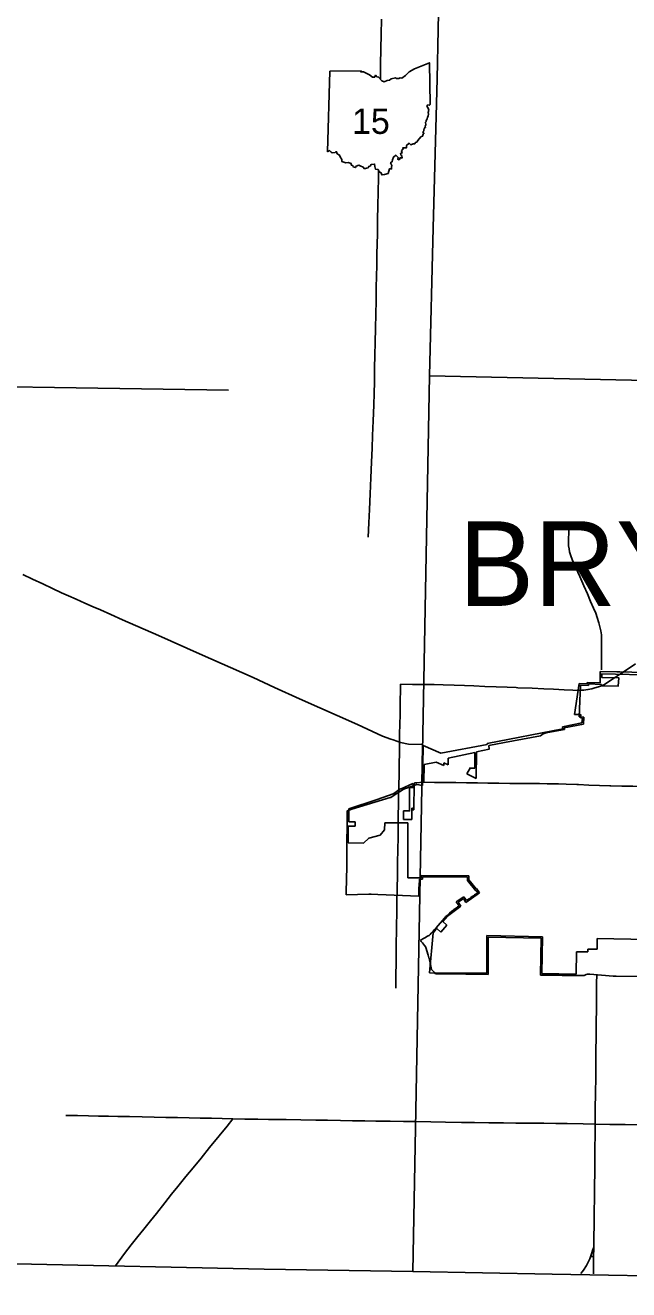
# Model space of a CAD drawing. Extents: x -232 to 448, y 619 to 1059.
# Drawn here: x -131.55 to -109.62, y 850.56 to 896.53 of the extents above; entities that cross this region are included whole.
import ezdxf

# ---------------------------------------------------------------- set-up
doc = ezdxf.new("R2010")
doc.units = 0
doc.layers.add('Default', color=7, linetype='Continuous')

msp = doc.modelspace()

# ---------------------------------------------------------------- linework, layer by layer
at = {"layer": 'Default'}
for p, q in [((-120.564, 891.931), (-120.482, 894.86)), ((-120.564, 891.931), (-120.482, 894.86)), ((-111.422, 872.599), (-111.588, 871.475)), ((-111.129, 872.588), (-111.422, 872.599)), ((-111.378, 872.546), (-111.419, 871.39)), ((-111.079, 872.535), (-111.378, 872.546)), ((-111.127, 872.641), (-111.129, 872.588)), ((-110.655, 872.624), (-111.127, 872.641)), ((-111.078, 872.588), (-111.079, 872.535)), ((-110.606, 872.571), (-111.078, 872.588)), ((-110.608, 872.519), (-110.606, 872.571)), ((-111.321, 871.168), (-112.028, 871.028)), ((-111.263, 871.128), (-111.968, 870.987)), ((-111.588, 871.475), (-111.364, 871.471)), ((-111.419, 871.39), (-111.253, 871.384)), ((-111.364, 871.471), (-111.378, 871.359)), ((-111.378, 871.359), (-111.302, 871.339)), ((-111.302, 871.339), (-111.321, 871.168)), ((-111.253, 871.384), (-111.263, 871.128)), ((-112.013, 870.952), (-114.762, 870.422)), ((-112.028, 871.028), (-112.013, 870.952)), ((-111.968, 870.987), (-111.956, 870.928)), ((-116.618, 869.744), (-117.06, 869.655)), ((-116.336, 869.616), (-116.618, 869.744)), ((-116.189, 869.894), (-116.189, 869.65)), ((-117.06, 869.655), (-117.065, 869.013)), ((-116.189, 869.65), (-116.336, 869.722)), ((-115.508, 869.317), (-115.374, 869.546)), ((-115.166, 869.147), (-115.508, 869.317)), ((-117.417, 868.979), (-117.428, 868.011)), ((-118.769, 868.391), (-119.787, 868.043)), ((-119.787, 868.043), (-119.79, 867.569)), ((-117.806, 867.657), (-117.807, 867.969)), ((-117.498, 868.073), (-117.498, 867.657)), ((-119.79, 867.569), (-119.559, 867.569)), ((-119.559, 867.569), (-119.559, 867.411)), ((-118.493, 867.279), (-118.49, 867.536)), ((-118.49, 867.536), (-117.644, 867.533)), ((-117.498, 867.657), (-117.806, 867.657)), ((-117.644, 867.533), (-117.652, 865.542)), ((-119.812, 867.416), (-119.817, 866.805)), ((-119.559, 867.411), (-119.812, 867.416)), ((-119.256, 866.795), (-119.062, 866.982)), ((-119.062, 866.982), (-118.657, 867.083)), ((-118.657, 867.083), (-118.493, 867.279)), ((-119.817, 866.805), (-119.256, 866.795)), ((-117.167, 865.54), (-117.166, 865.622)), ((-117.166, 865.622), (-115.427, 865.616)), ((-115.427, 865.616), (-115.429, 865.46)), ((-117.652, 865.542), (-117.167, 865.54)), ((-117.225, 865.489), (-117.116, 865.489)), ((-117.116, 865.489), (-117.115, 865.571)), ((-117.115, 865.571), (-115.479, 865.564)), ((-115.479, 865.564), (-115.481, 865.442)), ((-115.481, 865.442), (-115.177, 865.071)), ((-115.429, 865.46), (-115.167, 865.14)), ((-115.167, 865.14), (-115.154, 865.149)), ((-115.154, 865.149), (-115.046, 864.996)), ((-115.618, 864.853), (-115.888, 864.665)), ((-115.631, 864.781), (-115.817, 864.652)), ((-115.538, 864.646), (-115.631, 864.781)), ((-115.518, 864.708), (-115.618, 864.853)), ((-115.177, 865.071), (-115.167, 865.078)), ((-115.167, 865.078), (-115.108, 864.995)), ((-115.888, 864.665), (-115.787, 864.519)), ((-115.817, 864.652), (-115.719, 864.511)), ((-116.23, 863.82), (-116.448, 863.56)), ((-116.376, 863.945), (-116.23, 863.82)), ((-116.731, 863.544), (-116.859, 862.083)), ((-116.448, 863.56), (-116.594, 863.696)), ((-114.775, 862.075), (-114.775, 863.438)), ((-114.775, 863.438), (-112.75, 863.395)), ((-114.724, 862.023), (-114.724, 863.386)), ((-114.724, 863.386), (-112.802, 863.345)), ((-112.802, 863.345), (-112.831, 862.001)), ((-112.75, 863.395), (-112.778, 862.054)), ((-110.772, 862.941), (-110.77, 863.327)), ((-110.77, 863.327), (-108.941, 863.29)), ((-111.532, 862.04), (-111.522, 862.847)), ((-111.522, 862.847), (-111.112, 862.842)), ((-111.112, 862.842), (-111.111, 862.945)), ((-111.111, 862.945), (-110.772, 862.941)), ((-116.859, 862.083), (-114.775, 862.075)), ((-112.778, 862.054), (-111.532, 862.04))]:
    msp.add_line(p, q, dxfattribs=at)
for points in [[(-115.954, 922.545), (-116.114, 916.14), (-116.231, 910.823), (-116.342, 905.4), (-116.47, 899.975), (-116.579, 894.589), (-116.727, 889.174), (-116.86, 883.788)], [(-118.603, 896.759), (-118.617, 896.197), (-118.625, 895.675), (-118.637, 895.113), (-118.648, 894.57)], [(-120.482, 894.86), (-119.346, 894.879), (-119.364, 894.844), (-119.256, 894.836), (-119.143, 894.774), (-119.046, 894.734), (-118.928, 894.641), (-118.858, 894.642), (-118.828, 894.718), (-118.774, 894.659), (-118.71, 894.649), (-118.599, 894.509), (-118.508, 894.478), (-118.398, 894.526), (-118.316, 894.534), (-118.257, 894.582), (-118.101, 894.622), (-118.057, 894.598), (-117.975, 894.603), (-117.933, 894.621), (-117.861, 894.605), (-117.734, 894.711), (-117.604, 894.837), (-117.403, 894.955), (-117.103, 895.068), (-116.866, 895.168), (-116.832, 893.648)], [(-120.482, 894.86), (-119.346, 894.879), (-119.364, 894.844), (-119.256, 894.836), (-119.143, 894.774), (-119.046, 894.734), (-118.928, 894.641), (-118.858, 894.642), (-118.828, 894.718), (-118.774, 894.659), (-118.71, 894.649), (-118.599, 894.509), (-118.508, 894.478), (-118.398, 894.526), (-118.316, 894.534), (-118.257, 894.582), (-118.101, 894.622), (-118.057, 894.598), (-117.975, 894.603), (-117.933, 894.621), (-117.861, 894.605), (-117.734, 894.711), (-117.604, 894.837), (-117.403, 894.955), (-117.103, 895.068), (-116.866, 895.168), (-116.832, 893.648)], [(-116.832, 893.648), (-116.867, 893.627), (-116.921, 893.637), (-116.958, 893.594), (-116.913, 893.523), (-116.891, 893.448), (-116.91, 893.365), (-116.892, 893.297), (-116.904, 893.24), (-116.939, 893.183), (-116.95, 893.128), (-116.979, 893.071), (-116.977, 893.039), (-117.005, 893.014), (-117, 892.919), (-117.014, 892.866), (-117.009, 892.821), (-117.054, 892.809), (-117.044, 892.771), (-117.072, 892.742), (-117.066, 892.692), (-117.099, 892.661), (-117.067, 892.597), (-117.092, 892.577), (-117.113, 892.499), (-117.171, 892.483), (-117.287, 892.341), (-117.327, 892.288), (-117.373, 892.275), (-117.399, 892.219), (-117.455, 892.219), (-117.54, 892.181), (-117.595, 892.247), (-117.692, 892.168), (-117.703, 892.076), (-117.826, 892.079), (-117.821, 892.033), (-117.848, 892.02), (-117.873, 891.973), (-117.858, 891.891), (-117.916, 891.87), (-117.909, 891.822), (-117.872, 891.793), (-117.856, 891.702), (-117.917, 891.721), (-117.966, 891.644), (-118.018, 891.662), (-118.001, 891.727), (-118.087, 891.805), (-118.169, 891.742), (-118.212, 891.642), (-118.213, 891.575), (-118.274, 891.534), (-118.235, 891.439), (-118.242, 891.373), (-118.24, 891.311), (-118.317, 891.313), (-118.363, 891.145)], [(-116.832, 893.648), (-116.867, 893.627), (-116.921, 893.637), (-116.958, 893.594), (-116.913, 893.523), (-116.891, 893.448), (-116.91, 893.365), (-116.892, 893.297), (-116.904, 893.24), (-116.939, 893.183), (-116.95, 893.128), (-116.979, 893.071), (-116.977, 893.039), (-117.005, 893.014), (-117, 892.919), (-117.014, 892.866), (-117.009, 892.821), (-117.054, 892.809), (-117.044, 892.771), (-117.072, 892.742), (-117.066, 892.692), (-117.099, 892.661), (-117.067, 892.597), (-117.092, 892.577), (-117.113, 892.499), (-117.171, 892.483), (-117.287, 892.341), (-117.327, 892.288), (-117.373, 892.275), (-117.399, 892.219), (-117.455, 892.219), (-117.54, 892.181), (-117.595, 892.247), (-117.692, 892.168), (-117.703, 892.076), (-117.826, 892.079), (-117.821, 892.033), (-117.848, 892.02), (-117.873, 891.973), (-117.858, 891.891), (-117.916, 891.87), (-117.909, 891.822), (-117.872, 891.793), (-117.856, 891.702), (-117.917, 891.721), (-117.966, 891.644), (-118.018, 891.662), (-118.001, 891.727), (-118.087, 891.805), (-118.169, 891.742), (-118.212, 891.642), (-118.213, 891.575), (-118.274, 891.534), (-118.235, 891.439), (-118.242, 891.373), (-118.24, 891.311), (-118.317, 891.313), (-118.363, 891.145)], [(-118.363, 891.145), (-118.496, 891.113), (-118.588, 891.094), (-118.62, 891.17), (-118.686, 891.21), (-118.729, 891.287), (-118.823, 891.298), (-118.846, 891.403), (-118.856, 891.489), (-118.985, 891.468), (-119.021, 891.415), (-119.067, 891.401), (-119.093, 891.349), (-119.156, 891.344), (-119.223, 891.319), (-119.267, 891.371), (-119.377, 891.423), (-119.426, 891.45), (-119.529, 891.408), (-119.551, 891.359), (-119.634, 891.381), (-119.653, 891.436), (-119.703, 891.452), (-119.714, 891.51), (-119.82, 891.541), (-119.901, 891.529), (-120.045, 891.576), (-120.053, 891.653), (-120.102, 891.746), (-120.128, 891.811), (-120.219, 891.861), (-120.237, 891.938), (-120.266, 891.936), (-120.292, 891.904), (-120.393, 891.89), (-120.433, 891.922), (-120.49, 891.976), (-120.564, 891.931)], [(-118.363, 891.145), (-118.496, 891.113), (-118.588, 891.094), (-118.62, 891.17), (-118.686, 891.21), (-118.729, 891.287), (-118.823, 891.298), (-118.846, 891.403), (-118.856, 891.489), (-118.985, 891.468), (-119.021, 891.415), (-119.067, 891.401), (-119.093, 891.349), (-119.156, 891.344), (-119.223, 891.319), (-119.267, 891.371), (-119.377, 891.423), (-119.426, 891.45), (-119.529, 891.408), (-119.551, 891.359), (-119.634, 891.381), (-119.653, 891.436), (-119.703, 891.452), (-119.714, 891.51), (-119.82, 891.541), (-119.901, 891.529), (-120.045, 891.576), (-120.053, 891.653), (-120.102, 891.746), (-120.128, 891.811), (-120.219, 891.861), (-120.237, 891.938), (-120.266, 891.936), (-120.292, 891.904), (-120.393, 891.89), (-120.433, 891.922), (-120.49, 891.976), (-120.564, 891.931)], [(-118.714, 891.261), (-118.719, 890.97), (-118.725, 890.484), (-118.737, 889.96), (-118.747, 889.489), (-118.754, 888.952), (-118.761, 888.578), (-118.773, 888.226), (-118.779, 887.817), (-118.785, 887.4), (-118.797, 887.007), (-118.805, 886.511), (-118.813, 886.028), (-118.825, 885.526), (-118.836, 885), (-118.845, 884.541), (-118.855, 884.066), (-118.863, 883.556), (-118.875, 883.163), (-118.888, 882.721), (-118.912, 882.15), (-118.929, 881.621), (-118.951, 881.159), (-118.97, 880.651), (-118.993, 880.086), (-119.022, 879.496), (-119.046, 878.929), (-119.07, 878.442), (-119.088, 877.921)], [(-124.162, 883.271), (-138.409, 883.491), (-145.829, 883.68), (-151.284, 883.773), (-151.442, 883.782), (-152.698, 883.802)], [(-116.86, 883.788), (-117.47, 851.221)], [(-116.86, 883.788), (-95.963, 883.341), (-84.441, 883.001)], [(-111.787, 878.438), (-111.787, 878.432), (-111.803, 878.131), (-111.81, 877.819), (-111.811, 877.706), (-111.81, 877.609), (-111.791, 877.502), (-111.77, 877.388), (-111.729, 877.249), (-111.673, 877.11), (-111.538, 876.814), (-111.4, 876.489), (-111.252, 876.153), (-111.124, 875.862), (-111.007, 875.583), (-110.901, 875.343), (-110.82, 875.16), (-110.765, 875), (-110.708, 874.807), (-110.671, 874.664), (-110.638, 874.517), (-110.616, 874.368), (-110.608, 874.22), (-110.608, 874.031), (-110.608, 873.907)], [(-131.643, 876.566), (-131.283, 876.393), (-130.918, 876.221), (-130.564, 876.054), (-130.241, 875.904), (-129.986, 875.787), (-129.698, 875.663), (-129.39, 875.526), (-129.087, 875.394), (-128.822, 875.276), (-128.445, 875.113), (-128.015, 874.918)], [(-128.015, 874.918), (-126.716, 874.351), (-125.223, 873.682), (-123.266, 872.817), (-122.496, 872.462), (-121.58, 872.046), (-119.479, 871.118), (-118.564, 870.689), (-118.27, 870.581)], [(-110.608, 873.907), (-110.609, 873.735), (-110.613, 873.384), (-110.616, 873.096)], [(-110.654, 873.036), (-110.655, 872.624)], [(-106.397, 872.895), (-106.503, 872.9), (-107.268, 872.934), (-107.365, 872.938), (-107.377, 872.939), (-108.525, 872.985), (-108.582, 872.988), (-108.634, 872.989), (-109.946, 873.026), (-110.048, 873.029), (-110.055, 873.029), (-110.654, 873.036)], [(-108.138, 871.687), (-108.124, 872.262), (-108.62, 872.262), (-108.597, 872.909), (-110.603, 872.952), (-110.603, 872.825), (-109.982, 872.812), (-110.006, 872.506), (-110.608, 872.519)], [(-110.105, 872.831), (-109.884, 872.975), (-109.601, 873.16), (-109.376, 873.313)], [(-117.92, 872.36), (-117.918, 872.524)], [(-117.918, 872.524), (-117.917, 872.579)], [(-117.917, 872.579), (-117.484, 872.57), (-117.061, 872.567), (-116.687, 872.562), (-116.36, 872.556), (-115.966, 872.539), (-115.584, 872.525), (-115.252, 872.515), (-114.847, 872.496), (-114.437, 872.482), (-114.037, 872.467), (-113.712, 872.454)], [(-113.712, 872.454), (-113.653, 872.451), (-113.125, 872.428), (-112.704, 872.409), (-112.352, 872.392), (-111.966, 872.374), (-111.652, 872.356), (-111.451, 872.35), (-111.366, 872.355), (-111.251, 872.364), (-111.102, 872.384), (-110.962, 872.411), (-110.852, 872.44), (-110.721, 872.481), (-110.609, 872.523), (-110.526, 872.557), (-110.429, 872.62), (-110.196, 872.771), (-110.105, 872.831)], [(-117.93, 871.544), (-117.927, 871.846), (-117.925, 872.034)], [(-117.925, 872.034), (-117.924, 872.088)], [(-117.924, 872.088), (-117.921, 872.244), (-117.92, 872.36)], [(-117.939, 871.107), (-117.939, 871.129), (-117.931, 871.462), (-117.93, 871.544)], [(-117.967, 869.362), (-117.962, 869.701), (-117.955, 870.061), (-117.949, 870.396), (-117.946, 870.768), (-117.939, 871.107)], [(-111.956, 870.928), (-112.617, 870.809), (-112.727, 870.772), (-112.833, 870.705), (-114.141, 870.458), (-114.706, 870.346)], [(-118.27, 870.581), (-118.184, 870.549), (-117.92, 870.452), (-117.622, 870.396), (-117.112, 870.389)], [(-117.112, 870.389), (-117.129, 869.581), (-117.14, 869.03)], [(-117.087, 870.346), (-117.11, 868.893)], [(-116.455, 870.07), (-117.087, 870.346)], [(-114.76, 870.391), (-116.455, 870.07)], [(-114.706, 870.346), (-114.698, 870.211), (-115.153, 870.114)], [(-114.762, 870.422), (-114.76, 870.391)], [(-115.22, 870.1), (-116.189, 869.894)], [(-115.374, 869.546), (-115.374, 869.525), (-115.22, 869.525), (-115.22, 870.1)], [(-115.153, 870.114), (-115.166, 869.147)], [(-117.986, 868.383), (-117.974, 868.892), (-117.968, 869.297), (-117.967, 869.362)], [(-116.336, 869.722), (-116.336, 869.616)], [(-117.11, 868.893), (-117.118, 868.893), (-117.136, 868.896), (-117.242, 868.914), (-117.323, 868.928), (-117.732, 868.787), (-117.796, 868.765), (-117.819, 868.75), (-118.183, 868.516), (-118.271, 868.459), (-118.288, 868.455), (-119.683, 868.031), (-119.743, 868.013), (-119.785, 867.999), (-119.849, 867.977)], [(-117.459, 868.965), (-117.547, 868.936), (-117.809, 868.808), (-117.934, 868.761), (-118.161, 868.607), (-118.18, 868.595), (-118.769, 868.391)], [(-117.807, 867.969), (-117.583, 867.969), (-117.583, 868.818), (-117.459, 868.818), (-117.459, 868.965)], [(-117.12, 869.013), (-117.317, 868.997), (-117.378, 868.991), (-117.417, 868.979)], [(-117.14, 869.03), (-117.14, 869.014), (-116.68, 869.008), (-116.265, 869.003), (-115.905, 868.998), (-115.515, 868.994), (-115.416, 868.993)], [(-117.065, 869.013), (-117.12, 869.013)], [(-115.416, 868.993), (-115.12, 868.988), (-114.741, 868.98), (-114.34, 868.976), (-113.937, 868.97), (-113.543, 868.968), (-113.198, 868.965), (-112.863, 868.963), (-112.587, 868.958)], [(-112.587, 868.958), (-112.511, 868.956), (-112.17, 868.95), (-111.889, 868.941), (-111.507, 868.929), (-111.447, 868.927)], [(-111.447, 868.927), (-111.072, 868.912), (-111.067, 868.912)], [(-111.067, 868.912), (-110.684, 868.9)], [(-110.684, 868.9), (-110.305, 868.882)], [(-110.305, 868.882), (-110.267, 868.881), (-109.876, 868.872)], [(-109.876, 868.872), (-109.871, 868.872), (-109.468, 868.866), (-109.109, 868.857), (-108.791, 868.847), (-108.423, 868.838), (-108.101, 868.83), (-107.826, 868.826)], [(-118.005, 866.98), (-118.003, 867.056), (-117.998, 867.444), (-117.997, 867.857), (-117.99, 868.159), (-117.986, 868.383)], [(-119.849, 867.977), (-119.849, 867.96), (-119.85, 867.64), (-119.85, 867.536), (-119.85, 867.534), (-119.868, 866.733), (-119.871, 866.63), (-119.87, 866.629), (-119.863, 866.041), (-119.862, 865.954), (-119.863, 865.932), (-119.887, 865.026), (-119.889, 864.966), (-119.891, 864.918)], [(-117.428, 868.011), (-117.481, 868.011), (-117.481, 868.073), (-117.498, 868.073)], [(-118.015, 866.493), (-118.013, 866.596), (-118.005, 866.98)], [(-118.053, 864.223), (-118.046, 864.706), (-118.039, 865.142), (-118.028, 865.63), (-118.02, 866.154), (-118.015, 866.493)], [(-117.253, 864.874), (-117.248, 865.13), (-117.246, 865.183), (-117.242, 865.244), (-117.225, 865.489)], [(-119.891, 864.918), (-119.072, 864.945), (-118.987, 864.947), (-118.735, 864.937), (-117.253, 864.874)], [(-115.046, 864.996), (-115.538, 864.646)], [(-115.108, 864.995), (-115.133, 864.978), (-115.177, 864.947), (-115.221, 864.916), (-115.265, 864.885), (-115.31, 864.854), (-115.354, 864.823), (-115.398, 864.792), (-115.443, 864.761), (-115.487, 864.729), (-115.518, 864.708)], [(-118.064, 863.467), (-118.058, 863.856), (-118.053, 864.217), (-118.053, 864.223)], [(-115.719, 864.511), (-116.208, 864.139), (-116.376, 863.945)], [(-115.787, 864.519), (-115.806, 864.506), (-115.842, 864.479), (-115.885, 864.447), (-115.929, 864.415), (-115.972, 864.383), (-116.016, 864.351), (-116.059, 864.319), (-116.14, 864.258), (-116.152, 864.246), (-116.188, 864.207), (-116.225, 864.167), (-116.262, 864.127), (-116.313, 864.072)], [(-116.313, 864.072), (-116.623, 863.723), (-116.659, 863.683), (-116.695, 863.642), (-116.731, 863.602), (-116.767, 863.561), (-116.803, 863.521), (-116.839, 863.481), (-116.869, 863.447), (-116.908, 863.425), (-116.956, 863.399), (-117.003, 863.372), (-117.05, 863.346), (-117.098, 863.32), (-117.145, 863.294), (-117.187, 863.271)], [(-118.069, 863.196), (-118.067, 863.304)], [(-118.067, 863.304), (-118.064, 863.451), (-118.064, 863.467)], [(-116.594, 863.696), (-116.628, 863.657), (-116.731, 863.544)], [(-118.073, 862.711), (-118.072, 862.926)], [(-118.072, 862.926), (-118.071, 863.071), (-118.069, 863.196)], [(-117.187, 863.271), (-117.164, 863.221)], [(-117.164, 863.221), (-117.121, 863.171), (-117.045, 863.081), (-116.996, 863.022), (-116.99, 863.005), (-116.908, 862.723), (-116.88, 862.625), (-116.877, 862.614), (-116.818, 862.326), (-116.794, 862.21), (-116.775, 862.189), (-116.695, 862.104), (-116.639, 862.045)], [(-118.078, 862.279), (-118.074, 862.572), (-118.073, 862.711)], [(-118.086, 861.524), (-118.084, 861.627), (-118.08, 862.112), (-118.079, 862.171)], [(-118.079, 862.171), (-118.078, 862.279)], [(-116.639, 862.045), (-116.564, 862.044), (-115.542, 862.031), (-115.506, 862.031), (-115.434, 862.03), (-114.724, 862.023)], [(-112.831, 862.001), (-112.799, 862.001), (-112.751, 862), (-112.692, 861.999), (-112.154, 861.994), (-112.141, 861.994), (-112.046, 861.993), (-111.293, 861.988), (-111.238, 861.987), (-111.17, 862.018), (-111.121, 862.04), (-111.04, 862.034), (-110.183, 861.963), (-110.178, 861.963), (-110.072, 861.961), (-109.319, 861.945)], [(-110.806, 860.041), (-110.802, 860.247), (-110.795, 860.81), (-110.794, 861.291), (-110.789, 861.729), (-110.785, 861.987)], [(-110.785, 861.987), (-110.785, 862.041)], [(-110.81, 859.61), (-110.809, 859.884), (-110.806, 860.041)], [(-110.837, 856.584), (-110.835, 857.129), (-110.827, 857.72), (-110.821, 858.273), (-110.815, 858.85), (-110.812, 859.378), (-110.81, 859.61)], [(-130.08, 856.9), (-129.657, 856.893), (-129.25, 856.882), (-128.887, 856.877), (-128.527, 856.87), (-128.193, 856.86)], [(-128.277, 851.43), (-127.95, 851.881), (-127.7, 852.194), (-127.458, 852.493), (-127.24, 852.765), (-127.001, 853.066), (-126.785, 853.333), (-126.482, 853.718), (-126.234, 854.033), (-126.007, 854.32), (-125.713, 854.678), (-125.452, 854.997), (-125.164, 855.35), (-124.852, 855.737), (-124.504, 856.162), (-124.22, 856.51), (-124.007, 856.779)], [(-128.193, 856.86), (-127.763, 856.857), (-127.309, 856.847), (-126.862, 856.839), (-126.441, 856.83), (-126.022, 856.823), (-125.598, 856.816), (-125.192, 856.806), (-124.789, 856.799), (-124.391, 856.789), (-124.007, 856.779)], [(-124.007, 856.779), (-123.571, 856.77), (-123.463, 856.768)], [(-123.463, 856.768), (-123.095, 856.761), (-122.717, 856.756), (-122.076, 856.746), (-121.538, 856.737), (-120.995, 856.731), (-120.572, 856.722), (-120.098, 856.715), (-119.664, 856.708), (-119.216, 856.702), (-118.812, 856.696), (-118.296, 856.688), (-117.807, 856.681), (-117.368, 856.674), (-116.817, 856.665), (-116.277, 856.656), (-115.694, 856.647), (-115.231, 856.638), (-114.705, 856.634), (-114.169, 856.628), (-113.723, 856.624), (-113.156, 856.617), (-112.711, 856.614), (-112.271, 856.608), (-111.858, 856.604), (-111.281, 856.592), (-110.837, 856.584)], [(-110.889, 852.422), (-110.889, 852.449), (-110.882, 852.948), (-110.876, 853.423), (-110.87, 853.877), (-110.861, 854.378), (-110.859, 854.799), (-110.852, 855.278), (-110.849, 855.719), (-110.843, 856.182), (-110.837, 856.584)], [(-110.837, 856.584), (-110.307, 856.572), (-109.757, 856.565)], [(-109.757, 856.565), (-109.746, 856.565), (-109.225, 856.555)], [(-110.899, 851.775), (-110.894, 852.079), (-110.889, 852.422)], [(-150.45, 851.844), (-144.81, 851.751), (-139.291, 851.653), (-131.891, 851.507), (-122.867, 851.316), (-117.47, 851.221)], [(-111.015, 851.756), (-110.977, 851.866), (-110.936, 851.984), (-110.894, 852.114)], [(-111.362, 851.154), (-111.26, 851.277), (-111.158, 851.444), (-111.088, 851.586), (-111.038, 851.685), (-111.015, 851.756), (-110.961, 851.769), (-110.899, 851.775)], [(-110.899, 851.775), (-110.901, 851.59), (-110.905, 851.329), (-110.897, 851.144)], [(-117.47, 851.221), (-112.406, 851.132), (-101.474, 850.932), (-96.717, 850.799), (-85.18, 850.564)]]:
    msp.add_lwpolyline(points, dxfattribs=at)

# ---------------------------------------------------------------- texts
for s, height, p in [('15', 0.9234, (-119.678, 892.584)), ('BRYAN', 3.078, (-115.805, 875.424))]:
    msp.add_text(s, height=height, dxfattribs=at).set_placement(p)

doc.saveas('drawing.dxf')
